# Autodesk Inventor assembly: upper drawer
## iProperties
Created: 2005-05
Part Number: upper drawer
Document SubType Name: Assembly
Designer: a.campbell
Manufacturer: Standard
Standards Organization: Custom
B_Out_Length: 1.0 mm
B_Out_Width: 1.0 mm
B_Out_Thickness: 1.0 mm
LENGTH: 1.0 mm
WIDTH: 1.0 mm
THICKNESS: 1.0 mm
Author: a.campbell
